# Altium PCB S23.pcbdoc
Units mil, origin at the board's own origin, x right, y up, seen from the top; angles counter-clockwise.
Board outline 1783.62 x 1784.84 mil, 2 copper layers (Top Layer, Bottom Layer); 2 components, 2 nets, 65 pads, 0 vias.
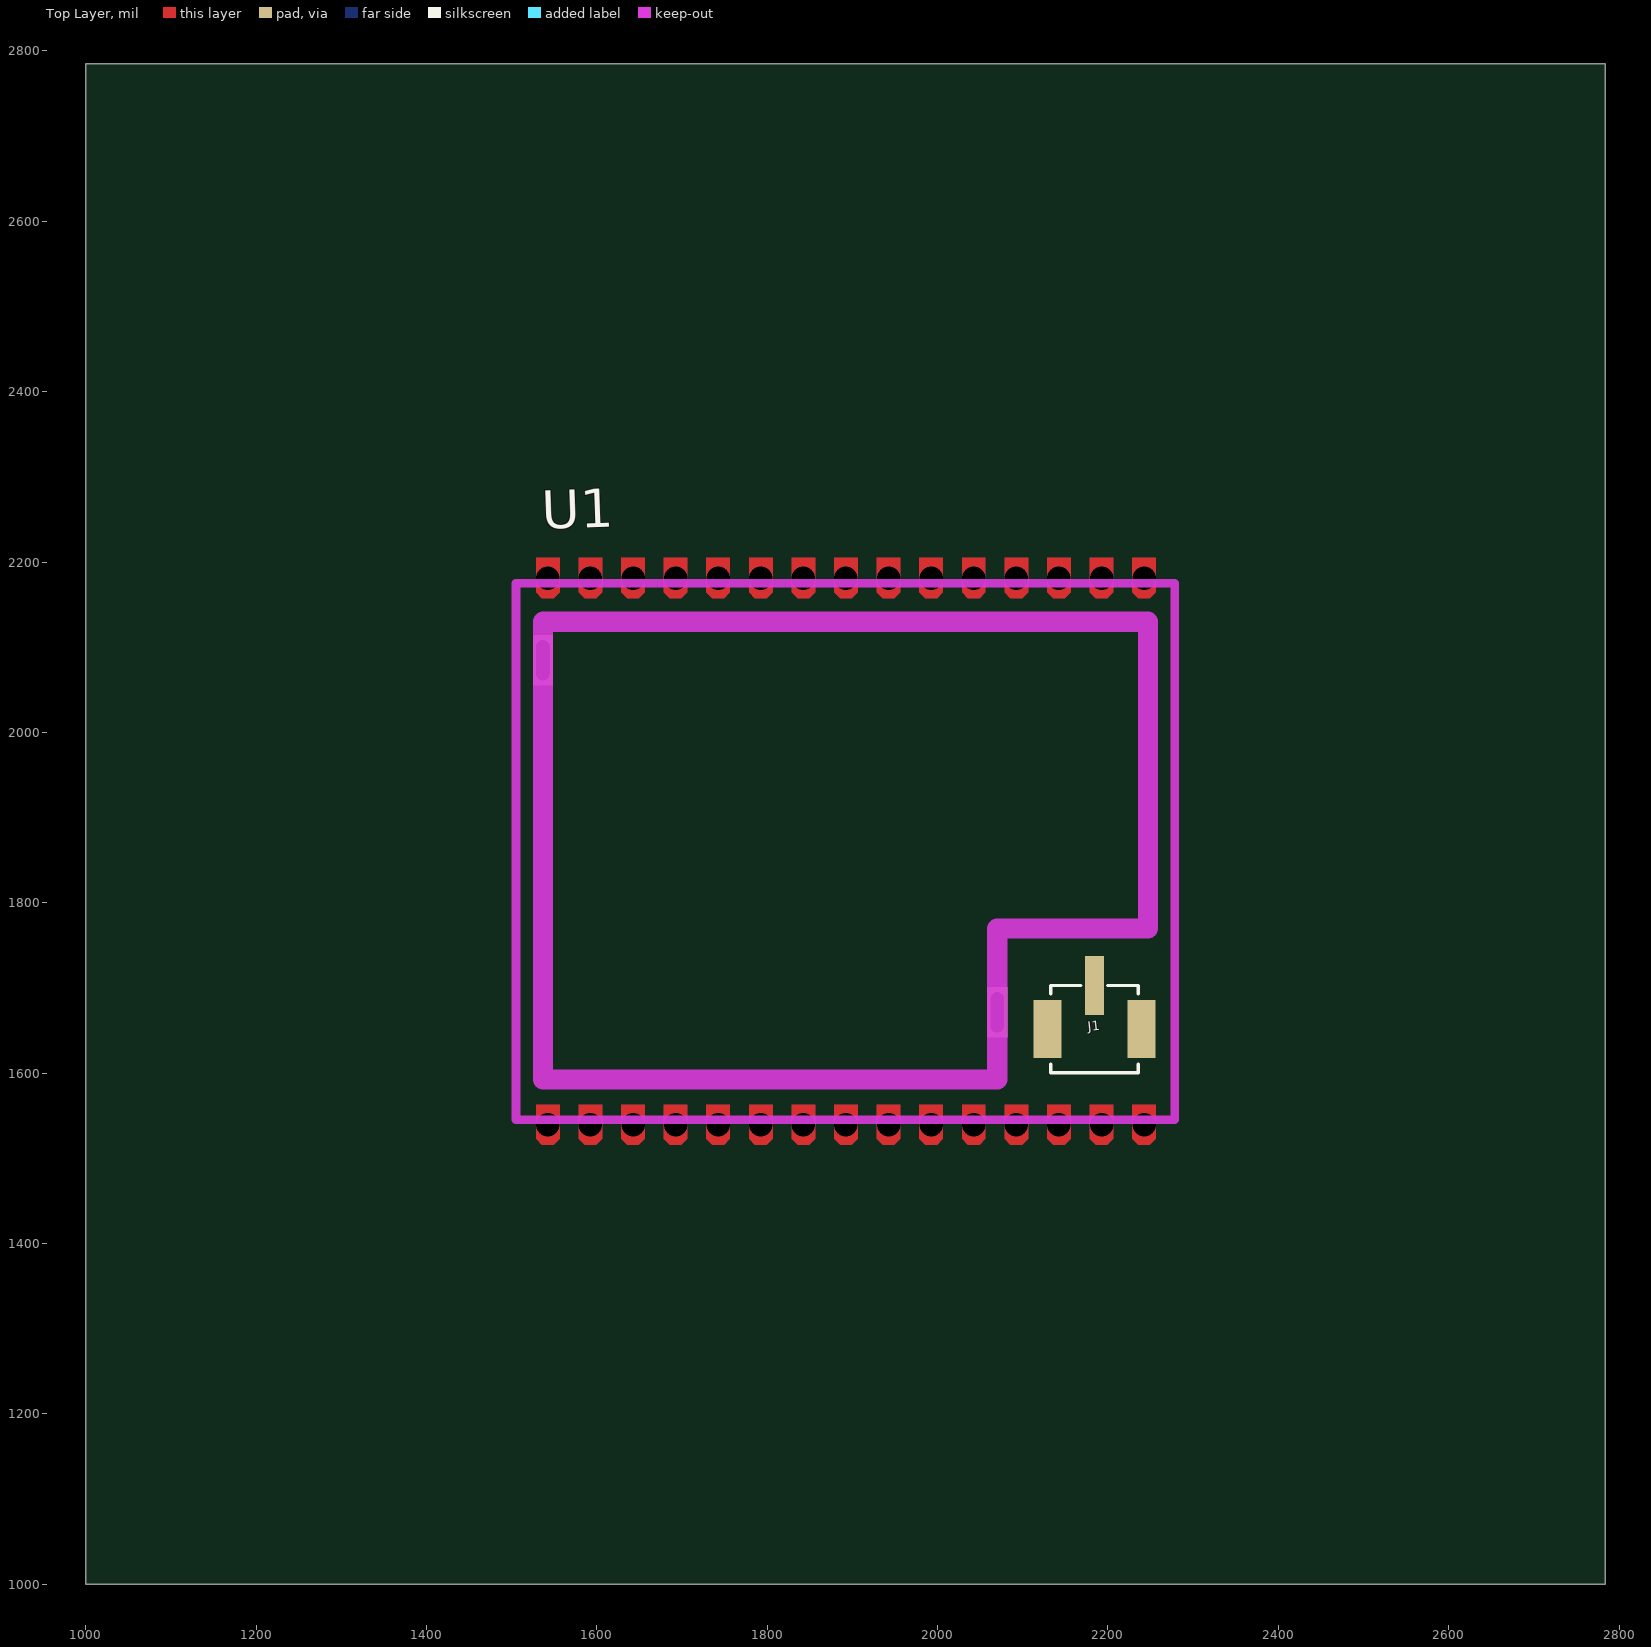
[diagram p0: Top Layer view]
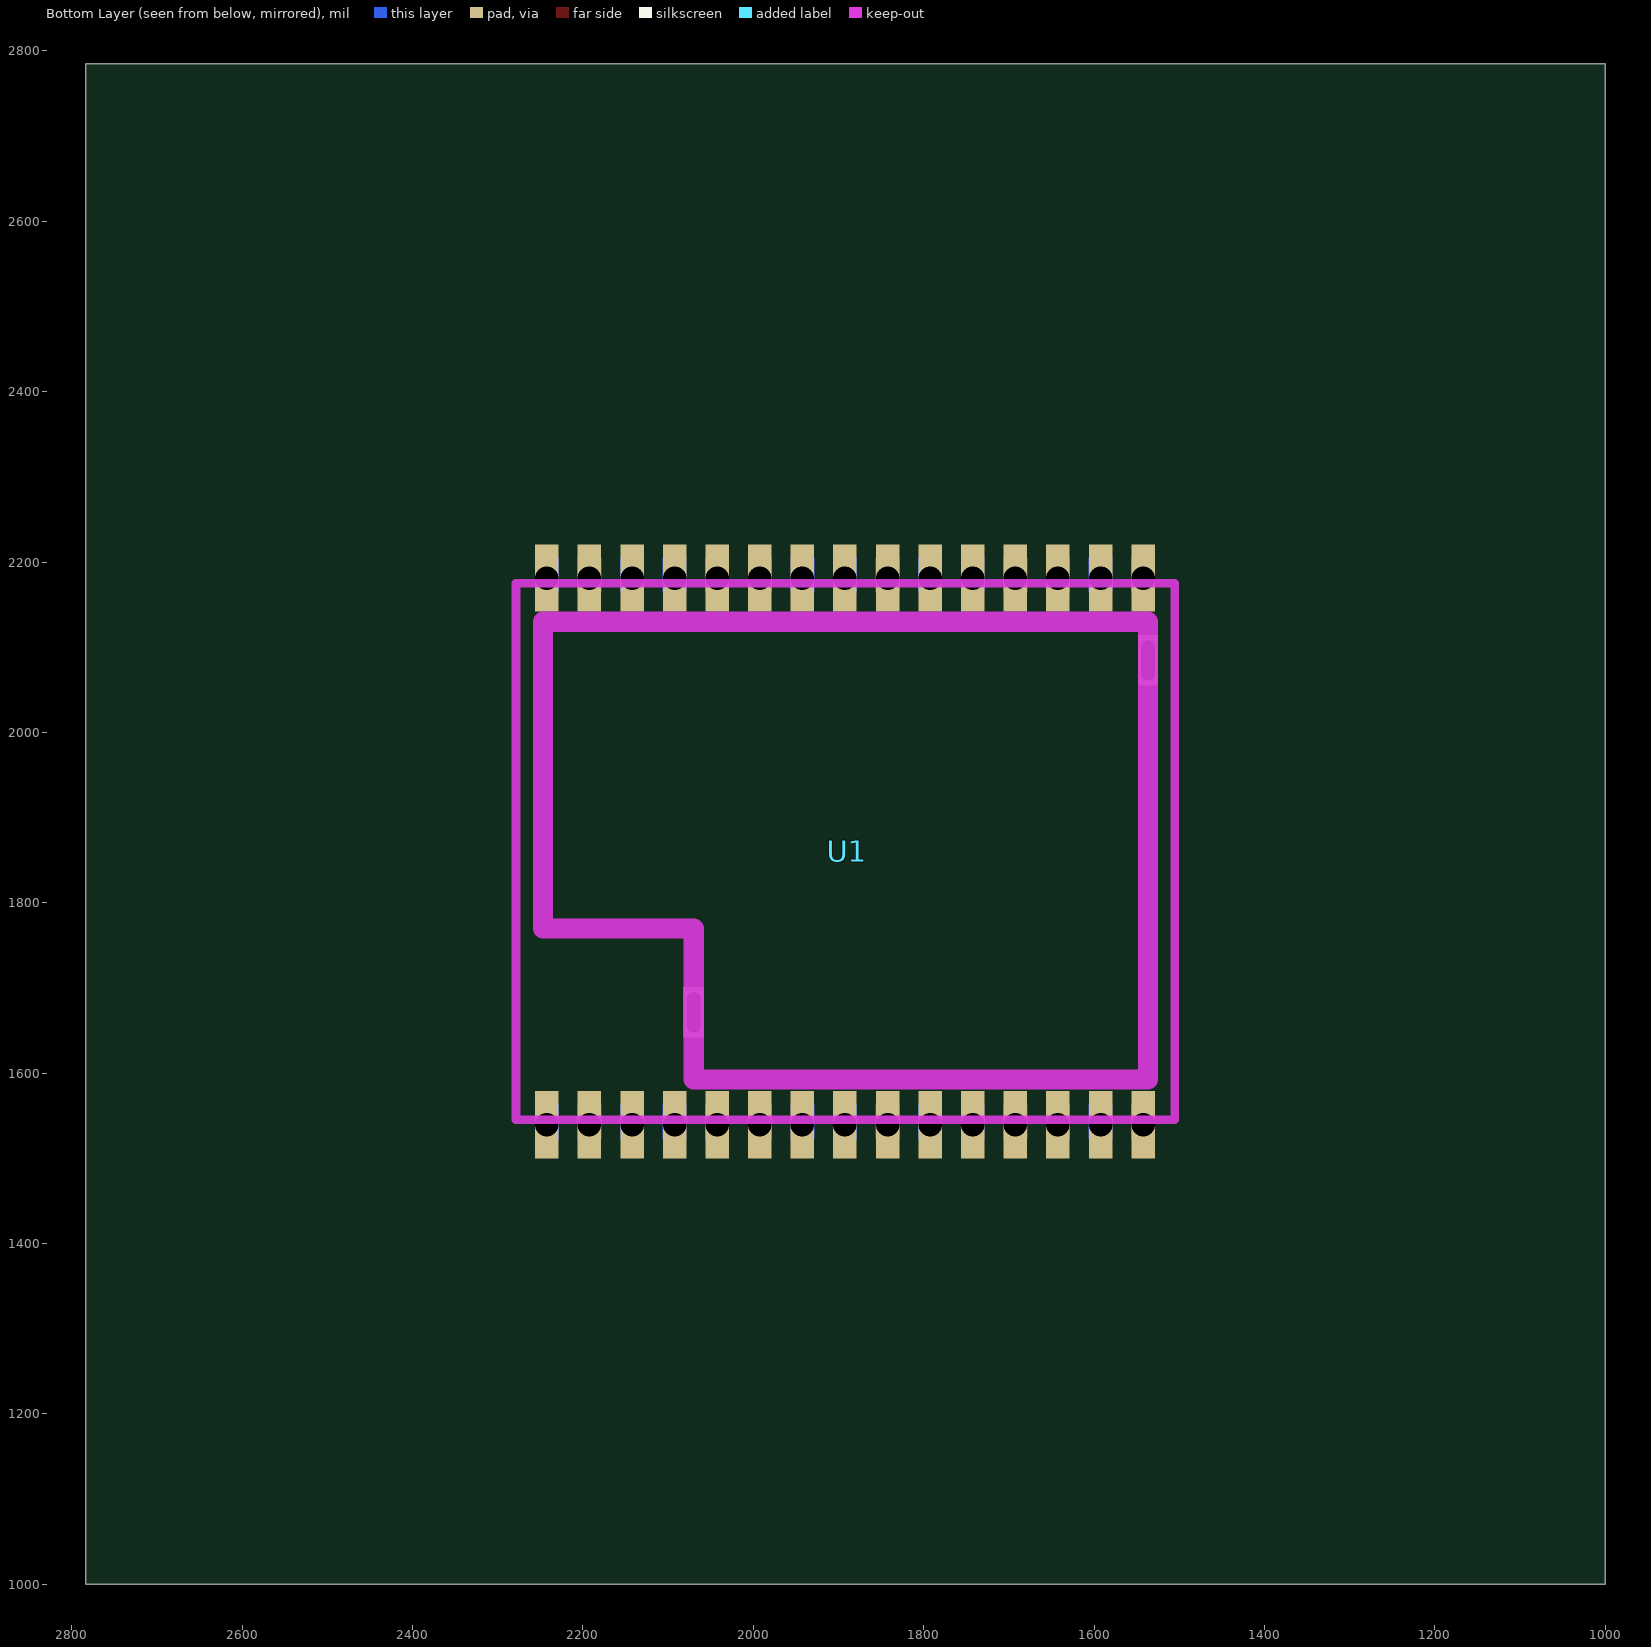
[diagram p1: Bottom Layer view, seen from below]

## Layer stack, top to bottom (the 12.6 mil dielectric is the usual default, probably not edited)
Top Layer: signal copper (thickness not stored)
Dielectric: dielectric 12.6, FR-4, Dk 4.8
Bottom Layer: signal copper (thickness not stored)

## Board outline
2783.62,1000 1000,1000 1000,2784.84 2783.62,2784.84

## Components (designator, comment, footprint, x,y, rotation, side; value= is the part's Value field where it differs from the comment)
J1 "ANT" IPEX 2184.13,1702.76 r0 top
U1 "S24-2020.4.1" S24-2020.4.1 1505,1545.28 r0 top

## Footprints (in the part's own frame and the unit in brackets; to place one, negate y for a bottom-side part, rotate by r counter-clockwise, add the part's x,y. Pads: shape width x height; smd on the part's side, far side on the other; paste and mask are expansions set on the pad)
IPEX [mil]
  rect 32.74x68.17 smd: 0(-55.11,-51.18)
  rect 32.73x68.17 smd: 0(55.12,-51.18)
  rect 21.83x69.07 smd: 1(0,0)
  silkscreen extent -51,-102 51,0
S24-2020.4.1 [mm]
  rect 0.6x1.5 hole 0.4 slot 1.2 at 90 deg: 0(0.8,13.7) 0(14.35,3.2)
  rect 0.7x2 smd far side: 1(0.95,-0.15) 2(2.22,-0.15) 3(3.49,-0.15) 4(4.76,-0.15) 5(6.03,-0.15) 6(7.3,-0.15) 7(8.57,-0.15) 8(9.84,-0.15) 9(11.11,-0.15) 10(12.38,-0.15) 11(13.65,-0.15) 12(14.92,-0.15) 13(16.19,-0.15) 14(17.46,-0.15) 15(18.73,-0.15) 16(18.73,16.15) 17(17.46,16.15) 18(16.19,16.15) 19(14.92,16.15) 20(13.65,16.15) 21(12.38,16.15) 22(11.11,16.15) 23(9.84,16.15) 24(8.57,16.15) 25(7.3,16.15) 26(6.03,16.15) 27(4.76,16.15) 28(3.49,16.15) 29(2.22,16.15) 30(0.95,16.15)
  round 0 hole 0.7: 1(0.95,-0.15) 2(2.22,-0.15) 3(3.49,-0.15) 4(4.76,-0.15) 5(6.03,-0.15) 6(7.3,-0.15) 7(8.57,-0.15) 8(9.84,-0.15) 9(11.11,-0.15) 10(12.38,-0.15) 11(13.65,-0.15) 12(14.92,-0.15) 13(16.19,-0.15) 14(17.46,-0.15) 15(18.73,-0.15) 16(18.73,16.15) 17(17.46,16.15) 18(16.19,16.15) 19(14.92,16.15) 20(13.65,16.15) 21(12.38,16.15) 22(11.11,16.15) 23(9.84,16.15) 24(8.57,16.15) 25(7.3,16.15) 26(6.03,16.15) 27(4.76,16.15) 28(3.49,16.15) 29(2.22,16.15) 30(0.95,16.15)
  Top Layer region: 1.3,0.45 1.3,-0.575 1.125,-0.75 0.775,-0.75 0.6,-0.575 0.6,0.45 0.775,0.45 1.125,0.45
  Top Layer region: 2.57,0.45 2.57,-0.575 2.395,-0.75 2.045,-0.75 1.87,-0.575 1.87,0.45 2.045,0.45 2.395,0.45
  Top Layer region: 3.84,0.45 3.84,-0.575 3.665,-0.75 3.315,-0.75 3.14,-0.575 3.14,0.45 3.315,0.45 3.665,0.45
  Top Layer region: 5.11,0.45 5.11,-0.575 4.935,-0.75 4.585,-0.75 4.41,-0.575 4.41,0.45 4.585,0.45 4.935,0.45
  Top Layer region: 6.38,0.45 6.38,-0.575 6.205,-0.75 5.855,-0.75 5.68,-0.575 5.68,0.45 5.855,0.45 6.205,0.45
  Top Layer region: 7.65,0.45 7.65,-0.575 7.475,-0.75 7.125,-0.75 6.95,-0.575 6.95,0.45 7.125,0.45 7.475,0.45
  Top Layer region: 8.92,0.45 8.92,-0.575 8.745,-0.75 8.395,-0.75 8.22,-0.575 8.22,0.45 8.395,0.45 8.745,0.45
  Top Layer region: 10.19,0.45 10.19,-0.575 10.015,-0.75 9.665,-0.75 9.49,-0.575 9.49,0.45 9.665,0.45 10.015,0.45
  Top Layer region: 11.46,0.45 11.46,-0.575 11.285,-0.75 10.935,-0.75 10.76,-0.575 10.76,0.45 10.935,0.45 11.285,0.45
  Top Layer region: 12.73,0.45 12.73,-0.575 12.555,-0.75 12.205,-0.75 12.03,-0.575 12.03,0.45 12.205,0.45 12.555,0.45
  Top Layer region: 14,0.45 14,-0.575 13.825,-0.75 13.475,-0.75 13.3,-0.575 13.3,0.45 13.475,0.45 13.825,0.45
  Top Layer region: 15.27,0.45 15.27,-0.575 15.095,-0.75 14.745,-0.75 14.57,-0.575 14.57,0.45 14.745,0.45 15.095,0.45
  Top Layer region: 16.54,0.45 16.54,-0.575 16.365,-0.75 16.015,-0.75 15.84,-0.575 15.84,0.45 16.015,0.45 16.365,0.45
  Top Layer region: 17.81,0.45 17.81,-0.575 17.635,-0.75 17.285,-0.75 17.11,-0.575 17.11,0.45 17.285,0.45 17.635,0.45
  Top Layer region: 19.08,0.45 19.08,-0.575 18.905,-0.75 18.555,-0.75 18.38,-0.575 18.38,0.45 18.555,0.45 18.905,0.45
  Top Layer region: 1.3,16.75 1.3,15.725 1.125,15.55 0.775,15.55 0.6,15.725 0.6,16.75 0.775,16.75 1.125,16.75
  Top Layer region: 2.57,16.75 2.57,15.725 2.395,15.55 2.045,15.55 1.87,15.725 1.87,16.75 2.045,16.75 2.395,16.75
  Top Layer region: 3.84,16.75 3.84,15.725 3.665,15.55 3.315,15.55 3.14,15.725 3.14,16.75 3.315,16.75 3.665,16.75
  Top Layer region: 5.11,16.75 5.11,15.725 4.935,15.55 4.585,15.55 4.41,15.725 4.41,16.75 4.585,16.75 4.935,16.75
  Top Layer region: 6.38,16.75 6.38,15.725 6.205,15.55 5.855,15.55 5.68,15.725 5.68,16.75 5.855,16.75 6.205,16.75
  Top Layer region: 7.65,16.75 7.65,15.725 7.475,15.55 7.125,15.55 6.95,15.725 6.95,16.75 7.125,16.75 7.475,16.75
  Top Layer region: 8.92,16.75 8.92,15.725 8.745,15.55 8.395,15.55 8.22,15.725 8.22,16.75 8.395,16.75 8.745,16.75
  Top Layer region: 10.19,16.75 10.19,15.725 10.015,15.55 9.665,15.55 9.49,15.725 9.49,16.75 9.665,16.75 10.015,16.75
  Top Layer region: 11.46,16.75 11.46,15.725 11.285,15.55 10.935,15.55 10.76,15.725 10.76,16.75 10.935,16.75 11.285,16.75
  Top Layer region: 12.73,16.75 12.73,15.725 12.555,15.55 12.205,15.55 12.03,15.725 12.03,16.75 12.205,16.75 12.555,16.75
  Top Layer region: 14,16.75 14,15.725 13.825,15.55 13.475,15.55 13.3,15.725 13.3,16.75 13.475,16.75 13.825,16.75
  Top Layer region: 15.27,16.75 15.27,15.725 15.095,15.55 14.745,15.55 14.57,15.725 14.57,16.75 14.745,16.75 15.095,16.75
  Top Layer region: 16.54,16.75 16.54,15.725 16.365,15.55 16.015,15.55 15.84,15.725 15.84,16.75 16.015,16.75 16.365,16.75
  Top Layer region: 17.81,16.75 17.81,15.725 17.635,15.55 17.285,15.55 17.11,15.725 17.11,16.75 17.285,16.75 17.635,16.75
  Top Layer region: 19.08,16.75 19.08,15.725 18.905,15.55 18.555,15.55 18.38,15.725 18.38,16.75 18.555,16.75 18.905,16.75
  Bottom Layer region: 1.3,0.45 1.3,-0.575 1.125,-0.75 0.775,-0.75 0.6,-0.575 0.6,0.45 0.775,0.45 1.125,0.45
  Bottom Layer region: 2.57,0.45 2.57,-0.575 2.395,-0.75 2.045,-0.75 1.87,-0.575 1.87,0.45 2.045,0.45 2.395,0.45
  Bottom Layer region: 3.84,0.45 3.84,-0.575 3.665,-0.75 3.315,-0.75 3.14,-0.575 3.14,0.45 3.315,0.45 3.665,0.45
  Bottom Layer region: 5.11,0.45 5.11,-0.575 4.935,-0.75 4.585,-0.75 4.41,-0.575 4.41,0.45 4.585,0.45 4.935,0.45
  Bottom Layer region: 6.38,0.45 6.38,-0.575 6.205,-0.75 5.855,-0.75 5.68,-0.575 5.68,0.45 5.855,0.45 6.205,0.45
  Bottom Layer region: 7.65,0.45 7.65,-0.575 7.475,-0.75 7.125,-0.75 6.95,-0.575 6.95,0.45 7.125,0.45 7.475,0.45
  Bottom Layer region: 8.92,0.45 8.92,-0.575 8.745,-0.75 8.395,-0.75 8.22,-0.575 8.22,0.45 8.395,0.45 8.745,0.45
  Bottom Layer region: 10.19,0.45 10.19,-0.575 10.015,-0.75 9.665,-0.75 9.49,-0.575 9.49,0.45 9.665,0.45 10.015,0.45
  Bottom Layer region: 11.46,0.45 11.46,-0.575 11.285,-0.75 10.935,-0.75 10.76,-0.575 10.76,0.45 10.935,0.45 11.285,0.45
  Bottom Layer region: 12.73,0.45 12.73,-0.575 12.555,-0.75 12.205,-0.75 12.03,-0.575 12.03,0.45 12.205,0.45 12.555,0.45
  Bottom Layer region: 14,0.45 14,-0.575 13.825,-0.75 13.475,-0.75 13.3,-0.575 13.3,0.45 13.475,0.45 13.825,0.45
  Bottom Layer region: 15.27,0.45 15.27,-0.575 15.095,-0.75 14.745,-0.75 14.57,-0.575 14.57,0.45 14.745,0.45 15.095,0.45
  Bottom Layer region: 16.54,0.45 16.54,-0.575 16.365,-0.75 16.015,-0.75 15.84,-0.575 15.84,0.45 16.015,0.45 16.365,0.45
  Bottom Layer region: 17.81,0.45 17.81,-0.575 17.635,-0.75 17.285,-0.75 17.11,-0.575 17.11,0.45 17.285,0.45 17.635,0.45
  Bottom Layer region: 19.08,0.45 19.08,-0.575 18.905,-0.75 18.555,-0.75 18.38,-0.575 18.38,0.45 18.555,0.45 18.905,0.45
  Bottom Layer region: 1.3,16.75 1.3,15.725 1.125,15.55 0.775,15.55 0.6,15.725 0.6,16.75 0.775,16.75 1.125,16.75
  Bottom Layer region: 2.57,16.75 2.57,15.725 2.395,15.55 2.045,15.55 1.87,15.725 1.87,16.75 2.045,16.75 2.395,16.75
  Bottom Layer region: 3.84,16.75 3.84,15.725 3.665,15.55 3.315,15.55 3.14,15.725 3.14,16.75 3.315,16.75 3.665,16.75
  Bottom Layer region: 5.11,16.75 5.11,15.725 4.935,15.55 4.585,15.55 4.41,15.725 4.41,16.75 4.585,16.75 4.935,16.75
  Bottom Layer region: 6.38,16.75 6.38,15.725 6.205,15.55 5.855,15.55 5.68,15.725 5.68,16.75 5.855,16.75 6.205,16.75
  Bottom Layer region: 7.65,16.75 7.65,15.725 7.475,15.55 7.125,15.55 6.95,15.725 6.95,16.75 7.125,16.75 7.475,16.75
  Bottom Layer region: 8.92,16.75 8.92,15.725 8.745,15.55 8.395,15.55 8.22,15.725 8.22,16.75 8.395,16.75 8.745,16.75
  Bottom Layer region: 10.19,16.75 10.19,15.725 10.015,15.55 9.665,15.55 9.49,15.725 9.49,16.75 9.665,16.75 10.015,16.75
  Bottom Layer region: 11.46,16.75 11.46,15.725 11.285,15.55 10.935,15.55 10.76,15.725 10.76,16.75 10.935,16.75 11.285,16.75
  Bottom Layer region: 12.73,16.75 12.73,15.725 12.555,15.55 12.205,15.55 12.03,15.725 12.03,16.75 12.205,16.75 12.555,16.75
  Bottom Layer region: 14,16.75 14,15.725 13.825,15.55 13.475,15.55 13.3,15.725 13.3,16.75 13.475,16.75 13.825,16.75
  Bottom Layer region: 15.27,16.75 15.27,15.725 15.095,15.55 14.745,15.55 14.57,15.725 14.57,16.75 14.745,16.75 15.095,16.75
  Bottom Layer region: 16.54,16.75 16.54,15.725 16.365,15.55 16.015,15.55 15.84,15.725 15.84,16.75 16.015,16.75 16.365,16.75
  Bottom Layer region: 17.81,16.75 17.81,15.725 17.635,15.55 17.285,15.55 17.11,15.725 17.11,16.75 17.285,16.75 17.635,16.75
  Bottom Layer region: 19.08,16.75 19.08,15.725 18.905,15.55 18.555,15.55 18.38,15.725 18.38,16.75 18.555,16.75 18.905,16.75
  Keep-Out Layer lines w0.254: 0,0 0,16 19.65,16 19.65,0 0,0
  Keep-Out Layer lines w0.6: 0.8,14.8 0.8,1.2 14.35,1.2 14.35,5.7 18.85,5.7 18.85,14.8 ; 0.8,14.85 18.85,14.85

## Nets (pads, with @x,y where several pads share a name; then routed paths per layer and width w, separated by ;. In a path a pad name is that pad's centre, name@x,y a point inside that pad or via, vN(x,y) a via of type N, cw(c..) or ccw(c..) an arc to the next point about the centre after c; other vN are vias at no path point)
ANT: J1.1
GND: J1.0
pads on no net: U1.0 U1.1 U1.2 U1.3 U1.4 U1.5 U1.6 U1.7 U1.8 U1.9 U1.10 U1.11 U1.12 U1.13 U1.14 U1.15 U1.16 U1.17 U1.18 U1.19 U1.20 U1.21 U1.22 U1.23 U1.24 U1.25 U1.26 U1.27 U1.28 U1.29 U1.30

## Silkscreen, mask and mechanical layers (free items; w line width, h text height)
Document:
  lines w0.1: 1890.81,1891.42 1892.81,1893.42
